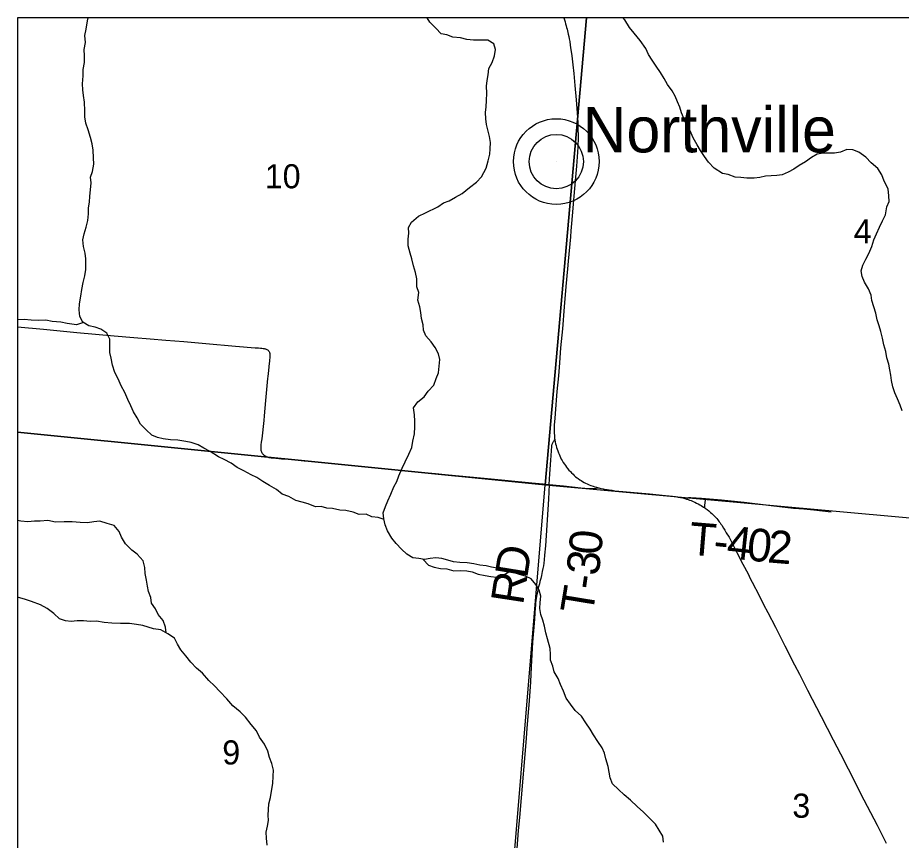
# Model space of a CAD drawing. Extents: x 0 to 1067, y 0 to 440.
# Drawn here: x 798.04 to 799.575, y 356.173 to 357.602 of the extents above; entities that cross this region are included whole.
import ezdxf

# ---------------------------------------------------------------- set-up
doc = ezdxf.new("R2010")
doc.units = 0
for name, color, linetype in [('GM_X_Minor_River', 7, 'Continuous'), ('GM_X_Section', 7, 'Continuous'), ('GM_X_Section_Text', 7, 'Continuous'), ('GM_X_State_Route', 7, 'Continuous'), ('GM_X_Township_Road', 7, 'Continuous'), ('GM_X_Township_Road_Text', 7, 'Continuous'), ('GM_X_Unincorporated', 7, 'Continuous'), ('GM_X_Unincorporated_Location', 7, 'Continuous'), ('GM_X_Unincorporated_Text', 7, 'Continuous'), ('GM_X_US_Shield', 7, 'Continuous')]:
    doc.layers.add(name, color=color, linetype=linetype)

msp = doc.modelspace()

# ---------------------------------------------------------------- linework, layer by layer
at = {"layer": 'GM_X_Minor_River'}
for points in [[(798.1593, 357.5822), (798.1612, 357.5969), (798.1625, 357.6021)], [(798.742, 357.0794), (798.7404, 357.09), (798.7388, 357.0999), (798.7354, 357.1114), (798.7373, 357.1246), (798.7338, 357.1346), (798.7334, 357.1482), (798.7311, 357.1593), (798.7281, 357.1711), (798.725, 357.1834), (798.7222, 357.1929), (798.7185, 357.2059), (798.7184, 357.2173), (798.7195, 357.2279), (798.719, 357.2374), (798.7242, 357.2471), (798.7367, 357.2573), (798.7486, 357.2634), (798.7702, 357.2733), (798.7802, 357.2802), (798.7898, 357.2841), (798.8006, 357.2902), (798.8126, 357.2967), (798.8254, 357.3069), (798.8371, 357.3161), (798.8457, 357.3257), (798.8541, 357.3409), (798.8576, 357.3537), (798.8602, 357.365), (798.8608, 357.3745), (798.8615, 357.385), (798.8599, 357.3957), (798.8569, 357.4072), (798.8549, 357.4167), (798.8533, 357.4266), (798.8528, 357.4372), (798.8539, 357.447), (798.8546, 357.458), (798.855, 357.4709), (798.8549, 357.4834), (798.8556, 357.4928), (798.8574, 357.503), (798.8589, 357.5139), (798.8645, 357.5244), (798.8683, 357.5356), (798.8705, 357.5469), (798.8674, 357.5565), (798.8569, 357.5632), (798.8467, 357.5632), (798.8319, 357.5632), (798.8205, 357.5643), (798.8092, 357.5669), (798.7964, 357.5684), (798.7859, 357.5722), (798.7761, 357.574), (798.7665, 357.5841), (798.7562, 357.5943), (798.7515, 357.6021)], [(799.2503, 357.3409), (799.2404, 357.351), (799.2334, 357.3607), (799.2262, 357.3712), (799.2208, 357.3812), (799.2139, 357.3935), (799.2086, 357.4054), (799.2021, 357.4158), (799.1982, 357.4258), (799.1936, 357.4369), (799.1904, 357.4465), (799.1862, 357.4561), (799.1827, 357.4657), (799.1773, 357.4753), (799.1692, 357.4861), (799.1635, 357.4965), (799.157, 357.507), (799.1497, 357.5178), (799.1424, 357.5282), (799.1362, 357.5379), (799.1316, 357.5486), (799.1214, 357.5622), (799.1112, 357.575), (799.1031, 357.5851), (799.0948, 357.5982), (799.0919, 357.6021)], [(798.6766, 356.7304), (798.6666, 356.7338), (798.6556, 356.7353), (798.6455, 356.7398), (798.6333, 356.7394), (798.6228, 356.7431), (798.6104, 356.7458), (798.5998, 356.7465), (798.5869, 356.7495), (798.5771, 356.7502), (798.5673, 356.7532), (798.5578, 356.7527), (798.5451, 356.7576), (798.5345, 356.7606), (798.5232, 356.7632), (798.5113, 356.7704), (798.4996, 356.7746), (798.4896, 356.7828), (798.4777, 356.7893), (798.4661, 356.7965), (798.4557, 356.8032), (798.446, 356.8081), (798.4329, 356.8149), (798.4213, 356.821), (798.4109, 356.8281), (798.3989, 356.8346), (798.3892, 356.8394), (798.3743, 356.8486), (798.3635, 356.8542), (798.3538, 356.8602), (798.3418, 356.864), (798.332, 356.8662), (798.3184, 356.8685), (798.3055, 356.8689), (798.293, 356.8708), (798.2832, 356.8726), (798.2734, 356.8767), (798.2635, 356.8861), (798.2535, 356.8963), (798.2478, 356.9071), (798.2416, 356.9175), (798.237, 356.9279), (798.2313, 356.939), (798.2263, 356.9513), (798.2198, 356.9625), (798.2145, 356.9748), (798.2091, 356.986), (798.2049, 356.9986), (798.2026, 357.0108), (798.2003, 357.0207), (798.2002, 357.0321), (798.2002, 357.0439), (798.1952, 357.0539), (798.1848, 357.061), (798.1746, 357.0644), (798.1637, 357.0666), (798.1533, 357.0733), (798.1479, 357.083), (798.1471, 357.0944), (798.1474, 357.105), (798.15, 357.1182), (798.1515, 357.1302), (798.1538, 357.1423), (798.1568, 357.1536), (798.1583, 357.1649), (798.1584, 357.1831), (798.1572, 357.1933), (798.1545, 357.2044), (798.1533, 357.2162), (798.1555, 357.2264), (798.1593, 357.238), (798.1623, 357.2496), (798.163, 357.2614), (798.1633, 357.2716), (798.1651, 357.2814), (798.1654, 357.292), (798.1665, 357.3033), (798.1677, 357.3154), (798.1668, 357.3249), (798.1701, 357.335), (798.1724, 357.3474), (798.1716, 357.3584), (798.1712, 357.3721), (798.1693, 357.3827), (798.1666, 357.3938), (798.1628, 357.4072), (798.1586, 357.419), (798.157, 357.43), (798.1569, 357.4403), (798.1563, 357.4554), (798.1547, 357.4668), (798.1531, 357.4767), (798.1527, 357.4873), (798.1538, 357.5013), (798.1541, 357.5119), (798.156, 357.5243), (798.1564, 357.5361), (798.1559, 357.5471), (798.1582, 357.5591), (798.157, 357.5709), (798.1593, 357.5822)], [(799.5771, 356.9191), (799.5736, 356.9291), (799.5689, 356.9398), (799.5639, 356.9506), (799.5605, 356.9609), (799.5585, 356.9716), (799.5569, 356.9811), (799.5556, 356.9907), (799.5537, 357.0002), (799.5502, 357.0113), (799.5486, 357.022), (799.5448, 357.0338), (799.5425, 357.0453), (799.5398, 357.0571), (799.537, 357.0671), (799.5332, 357.0774), (799.5312, 357.0888), (799.5278, 357.0996), (799.5243, 357.1107), (799.5231, 357.1202), (799.5181, 357.1309), (799.5112, 357.1429), (799.5073, 357.1525), (799.5057, 357.1624), (799.5087, 357.1725), (799.5135, 357.1826), (799.5188, 357.1927), (799.5244, 357.2047), (799.5278, 357.2163), (799.5323, 357.2264), (799.5372, 357.2384), (799.5428, 357.2492), (799.5477, 357.2597), (799.5504, 357.2733), (799.5544, 357.283), (799.5536, 357.2929), (799.5524, 357.305), (799.5456, 357.3181), (799.5414, 357.3292), (799.5345, 357.3401), (799.523, 357.3499), (799.5135, 357.3596), (799.5016, 357.3687), (799.4911, 357.3724), (799.4808, 357.3731), (799.4697, 357.3685), (799.4594, 357.3665), (799.4488, 357.3665), (799.4393, 357.3667), (799.429, 357.3648), (799.4193, 357.359), (799.4089, 357.3517), (799.3981, 357.3456), (799.3884, 357.3391), (799.3787, 357.334), (799.3684, 357.3294), (799.3588, 357.3278), (799.3394, 357.3269), (799.3295, 357.3245), (799.3196, 357.3233), (799.3067, 357.3233), (799.2965, 357.3244), (799.2866, 357.325), (799.2743, 357.3296), (799.2645, 357.3317), (799.2503, 357.3409)], [(798.1547, 357.0724), (798.1421, 357.0684), (798.1262, 357.0708), (798.1149, 357.073), (798.1002, 357.0746), (798.0892, 357.0764), (798.0763, 357.0761), (798.0638, 357.0768), (798.0517, 357.078), (798.0403, 357.0772), (798.0401, 357.0772)], [(799.1611, 356.1806), (799.1545, 356.1911), (799.148, 356.2012), (799.1384, 356.211), (799.1277, 356.2223), (799.1163, 356.2322), (799.1048, 356.2428), (799.0937, 356.2522), (799.0837, 356.2616), (799.0738, 356.2714), (799.0695, 356.2815), (799.0675, 356.2914), (799.0663, 356.3013), (799.0622, 356.3147), (799.0598, 356.3243), (799.0555, 356.3339), (799.0479, 356.3448), (799.0406, 356.3564), (799.0348, 356.3661), (799.0272, 356.377), (799.0196, 356.389), (799.0085, 356.3984), (799.0008, 356.4097), (798.9928, 356.4202), (798.9882, 356.4321), (798.9832, 356.444), (798.979, 356.4544), (798.9725, 356.466), (798.9701, 356.4759), (798.9659, 356.4863), (798.9658, 356.4958), (798.965, 356.5065), (798.9609, 356.5229), (798.9578, 356.5337), (798.9555, 356.5451), (798.9524, 356.5555), (798.9489, 356.5654), (798.9476, 356.5757), (798.9479, 356.586), (798.949, 356.5973), (798.9463, 356.6077), (798.9405, 356.6173), (798.9325, 356.6271), (798.9224, 356.6319), (798.9122, 356.6349), (798.8979, 356.6395), (798.8873, 356.6406), (798.8765, 356.6455), (798.8636, 356.6474), (798.8538, 356.6499), (798.8432, 356.651), (798.8327, 356.6532), (798.8213, 356.6551), (798.8085, 356.6559), (798.7971, 356.657), (798.7873, 356.6599), (798.7772, 356.6625), (798.7666, 356.664), (798.7567, 356.6628), (798.7471, 356.6612), (798.7373, 356.6626), (798.7267, 356.664), (798.7163, 356.6701), (798.7067, 356.6787), (798.6978, 356.6885), (798.6902, 356.6982), (798.6826, 356.7109), (798.6787, 356.7209), (798.6764, 356.7316), (798.6751, 356.7423), (798.6793, 356.7532), (798.6833, 356.7629), (798.6886, 356.7745), (798.6939, 356.7869), (798.6988, 356.7966), (798.7025, 356.8063), (798.7082, 356.8194), (798.7134, 356.8307), (798.7195, 356.8441), (798.7252, 356.8557), (798.7266, 356.8667), (798.7297, 356.8795), (798.7304, 356.8912), (798.7303, 356.9015), (798.7295, 356.9125), (798.7276, 356.9243), (798.7351, 356.9347), (798.7464, 356.9435), (798.7535, 356.9535), (798.7633, 356.9635), (798.767, 356.9751), (798.7715, 356.9852), (798.7726, 356.9965), (798.7733, 357.0083), (798.7713, 357.0182), (798.7656, 357.029), (798.7583, 357.0391), (798.7495, 357.0496), (798.7452, 357.0592), (798.7448, 357.0687), (798.742, 357.0794)], [(798.2979, 356.5337), (798.297, 356.5435), (798.2928, 356.5551), (798.2844, 356.5652), (798.2793, 356.5752), (798.2728, 356.5849), (798.2712, 356.5952), (798.2673, 356.6052), (798.2657, 356.6147), (798.2637, 356.625), (798.2618, 356.6365), (798.261, 356.6471), (798.2579, 356.6586), (798.248, 356.6703), (798.2383, 356.6774), (798.2277, 356.6884), (798.2208, 356.7), (798.2165, 356.7096), (798.2077, 356.7198), (798.1957, 356.7235), (798.1829, 356.7273), (798.1726, 356.7265), (798.1615, 356.7246), (798.1487, 356.7254), (798.135, 356.7262), (798.121, 356.7262), (798.1058, 356.7259), (798.0926, 356.7286), (798.0793, 356.7275), (798.0694, 356.7274), (798.058, 356.7266), (798.0455, 356.7278), (798.0401, 356.7288)], [(798.7441, 356.6618), (798.7445, 356.6612), (798.754, 356.6511), (798.7638, 356.6474), (798.7747, 356.6451), (798.7857, 356.6448), (798.7978, 356.6414), (798.8096, 356.6418), (798.8202, 356.6411), (798.83, 356.6397), (798.8401, 356.6356), (798.8522, 356.6329), (798.8624, 356.6315), (798.8722, 356.63), (798.8818, 356.6324), (798.8934, 356.6396), (798.8936, 356.6399)], [(798.4759, 356.2265), (798.4766, 356.2364), (798.4796, 356.2477), (798.481, 356.2587), (798.4837, 356.2719), (798.4841, 356.2848), (798.4848, 356.2951), (798.4817, 356.3066), (798.4774, 356.3173), (798.4747, 356.328), (798.469, 356.3404), (798.4603, 356.3524), (798.4553, 356.3632), (798.4457, 356.3745), (798.4362, 356.387), (798.4266, 356.3964), (798.4137, 356.407), (798.4038, 356.4191), (798.3916, 356.4316), (798.3821, 356.4414), (798.3721, 356.4508), (798.3611, 356.4633), (798.3507, 356.4724), (798.3411, 356.4829), (798.3324, 356.4938), (798.3236, 356.504), (798.3178, 356.514), (798.3124, 356.5245), (798.3008, 356.532), (798.2889, 356.5388), (798.276, 356.5404), (798.2576, 356.5463), (798.2467, 356.5481), (798.2342, 356.5496), (798.219, 356.5497), (798.2035, 356.5506), (798.1906, 356.5517), (798.177, 356.5541), (798.166, 356.5533), (798.1546, 356.5547), (798.1436, 356.5547), (798.1333, 356.5531), (798.1235, 356.5546), (798.113, 356.5579), (798.103, 356.5673), (798.0911, 356.5761), (798.0799, 356.5825), (798.0642, 356.5883), (798.054, 356.5916), (798.0401, 356.5956)], [(798.4737, 356.1647), (798.4726, 356.1769), (798.4721, 356.1875), (798.4739, 356.1977), (798.4757, 356.2076), (798.4753, 356.2171), (798.4759, 356.2265)], [(799.1623, 356.17), (799.1611, 356.1806)]]:
    msp.add_lwpolyline(points, dxfattribs=at)
at = {"layer": 'GM_X_Section'}
msp.add_lwpolyline([(798.9566, 356.7904), (799.9676, 356.6989), (799.8698, 355.7001), (798.8732, 355.7891)], close=True, dxfattribs=at)
at = {"layer": 'GM_X_State_Route'}
for points in [[(798.9887, 357.6021), (798.9889, 357.6017), (798.99, 357.5981), (798.9911, 357.5948), (798.9921, 357.5916), (798.993, 357.588), (798.9939, 357.5848), (798.9947, 357.582), (798.9954, 357.5794), (798.996, 357.5763), (798.9967, 357.5735), (798.9977, 357.5692), (798.9985, 357.5651), (798.9992, 357.5606), (799.0002, 357.5542), (799.0008, 357.5503), (799.0027, 357.5358), (799.0034, 357.5307), (799.0048, 357.52), (799.0061, 357.5052), (799.0082, 357.4842), (799.0105, 357.4594), (799.0117, 357.4441), (799.0128, 357.428), (799.0131, 357.4192), (799.0135, 357.4118), (799.0137, 357.3941), (799.0132, 357.378), (799.0129, 357.3684), (799.0123, 357.3601), (799.0111, 357.3439), (799.0089, 357.3186), (799.0065, 357.292), (799.0052, 357.2783), (799.0035, 357.258), (799.0023, 357.2445), (799.0013, 357.2318), (799.0003, 357.2215), (798.9992, 357.2091), (798.9975, 357.1915), (798.9964, 357.179), (798.9952, 357.1656), (798.9927, 357.1351), (798.9896, 357.1), (798.9865, 357.0617), (798.9835, 357.0289), (798.9812, 357.0027), (798.9795, 356.9799), (798.9771, 356.9526), (798.9738, 356.9144), (798.9731, 356.9056), (798.9723, 356.895), (798.9722, 356.8886), (798.9723, 356.8818), (798.9726, 356.8754), (798.9729, 356.8719), (798.9734, 356.8688), (798.974, 356.8653), (798.9747, 356.862), (798.9755, 356.8588), (798.9763, 356.8555), (798.9773, 356.8524), (798.9783, 356.8495), (798.9796, 356.8463), (798.9807, 356.8437), (798.9818, 356.841), (798.9831, 356.8382), (798.9846, 356.8351), (798.9859, 356.8328), (798.9878, 356.8296), (798.9899, 356.8267), (798.9917, 356.8241), (798.9935, 356.8215), (798.9955, 356.8188), (798.9978, 356.8162), (799.0003, 356.8136), (799.0024, 356.8113), (799.0051, 356.8089), (799.0071, 356.8069), (799.0095, 356.8048), (799.0121, 356.8027), (799.014, 356.8015), (799.0168, 356.7996), (799.0191, 356.798), (799.0216, 356.7965), (799.0242, 356.795), (799.0269, 356.7936), (799.0296, 356.7923), (799.0329, 356.7909), (799.0359, 356.7897), (799.0398, 356.7883), (799.0429, 356.7873), (799.0459, 356.7864), (799.0497, 356.7853), (799.0531, 356.7845), (799.0573, 356.7836), (799.0611, 356.7828), (799.0644, 356.7823), (799.0678, 356.7818), (799.0727, 356.7812), (799.0777, 356.7805), (799.0917, 356.779), (799.1379, 356.7749), (799.1655, 356.7722), (799.1721, 356.7715), (799.1778, 356.7708), (799.183, 356.7702), (799.1877, 356.7694), (799.1919, 356.7687), (799.196, 356.7678), (799.1993, 356.7669), (799.2024, 356.766), (799.2052, 356.7651), (799.2076, 356.7643), (799.2105, 356.7632), (799.2137, 356.7619), (799.2167, 356.7606), (799.2196, 356.7591), (799.2225, 356.7576), (799.2251, 356.7561), (799.2278, 356.7546), (799.2319, 356.7519), (799.2338, 356.7506), (799.2347, 356.75), (799.238, 356.7476), (799.2408, 356.7454), (799.2437, 356.7428), (799.246, 356.7407), (799.2483, 356.7386), (799.2507, 356.7363), (799.2527, 356.7343), (799.2546, 356.7322), (799.2565, 356.73), (799.2577, 356.7283), (799.2591, 356.7265), (799.2606, 356.7244), (799.262, 356.7223), (799.2633, 356.7205), (799.2664, 356.7156), (799.2687, 356.7121), (799.2713, 356.7075), (799.276, 356.6995), (799.2896, 356.6734), (799.3, 356.653), (799.309, 356.6359), (799.3129, 356.6282)], [(799.3129, 356.6282), (799.3164, 356.6214), (799.3281, 356.5982), (799.336, 356.5827), (799.3433, 356.5687), (799.3565, 356.5432), (799.3728, 356.5111), (799.3899, 356.478), (799.3982, 356.4616), (799.4123, 356.4341), (799.4361, 356.388), (799.4569, 356.3477), (799.4695, 356.3234), (799.4828, 356.2973), (799.5105, 356.2436), (799.5331, 356.1994), (799.5493, 356.1683)]]:
    msp.add_lwpolyline(points, dxfattribs=at)
at = {"layer": 'GM_X_Township_Road'}
for points in [[(799.7017, 353.7093), (799.8752, 355.6984), (799.9856, 356.8149), (800.0635, 357.6021), (798.0401, 357.6021), (798.0401, 353.8616)], [(798.0401, 357.0651), (798.0848, 357.0608), (798.1431, 357.0552), (798.2075, 357.0496), (798.2417, 357.0467), (798.2704, 357.0442), (798.2974, 357.042), (798.329, 357.0394), (798.3669, 357.0361), (798.4183, 357.0317), (798.4527, 357.0288), (798.4585, 357.0284), (798.462, 357.0281), (798.4641, 357.0279), (798.4664, 357.0277), (798.4681, 357.0274), (798.4694, 357.027), (798.4707, 357.0266), (798.4721, 357.0261), (798.4732, 357.0256), (798.4742, 357.0249), (798.4751, 357.0243), (798.476, 357.0235), (798.4765, 357.0229), (798.4771, 357.0221)], [(798.4771, 357.0221), (798.4776, 357.0211), (798.4779, 357.02), (798.4781, 357.0191), (798.4783, 357.0181), (798.4783, 357.0162), (798.4783, 357.0148), (798.4782, 357.0127), (798.4781, 357.0106), (798.4778, 357.0085), (798.4775, 357.0051), (798.4772, 357.0019), (798.4758, 356.9893), (798.4746, 356.9786), (798.4744, 356.9755), (798.4709, 356.9371), (798.4686, 356.9105), (798.4679, 356.9024), (798.4642, 356.8705), (798.4634, 356.8646), (798.4628, 356.8599), (798.4627, 356.8575), (798.4626, 356.8555), (798.4625, 356.8538), (798.4626, 356.8522), (798.4628, 356.8506), (798.4632, 356.8491), (798.4636, 356.8479), (798.4644, 356.8464), (798.4653, 356.8452), (798.4662, 356.844), (798.467, 356.8432), (798.468, 356.8423), (798.4691, 356.8416), (798.4703, 356.8409), (798.4715, 356.8402), (798.4729, 356.8395), (798.4741, 356.8391), (798.4752, 356.8387), (798.4767, 356.8384), (798.4785, 356.838), (798.4804, 356.8377), (798.4831, 356.8374), (798.4886, 356.8369), (798.4983, 356.8361), (798.511, 356.835), (798.5376, 356.8326), (798.5784, 356.8286), (798.6195, 356.8246), (798.678, 356.8188), (798.6919, 356.8174), (798.7066, 356.8159), (798.7215, 356.8145), (798.766, 356.8103), (798.7888, 356.8081), (798.8627, 356.8008), (798.9278, 356.7946), (798.9398, 356.7935), (798.9529, 356.7924), (798.9635, 356.7915)], [(798.9635, 356.7915), (798.9648, 356.8095), (798.9663, 356.8337), (798.9681, 356.8577), (798.9682, 356.8587), (798.9684, 356.8597), (798.9685, 356.8606), (798.9688, 356.8613), (798.9691, 356.8622), (798.9697, 356.8636), (798.9705, 356.8649), (798.9713, 356.866), (798.9721, 356.8671), (798.9734, 356.8688)], [(798.9635, 356.7915), (798.9621, 356.7655), (798.9569, 356.6847), (798.9555, 356.6687), (798.9548, 356.6606), (798.9541, 356.6544), (798.9535, 356.6497), (798.9527, 356.6452), (798.9515, 356.6399), (798.95, 356.6334), (798.9489, 356.6281), (798.9475, 356.6228), (798.9466, 356.6187), (798.9452, 356.6137), (798.944, 356.6088), (798.943, 356.6041), (798.9422, 356.6001), (798.9416, 356.5969), (798.941, 356.5932), (798.9405, 356.59), (798.94, 356.5859), (798.9395, 356.5809), (798.9393, 356.577), (798.9386, 356.5678), (798.9378, 356.5572), (798.9373, 356.5504), (798.9348, 356.5175), (798.9321, 356.4748), (798.9309, 356.4487), (798.9286, 356.4152), (798.9275, 356.4022), (798.9248, 356.3682), (798.9233, 356.3508), (798.9222, 356.336), (798.9146, 356.2469), (798.9118, 356.2128), (798.9098, 356.1905), (798.9071, 356.159)], [(798.9635, 356.7915), (798.9885, 356.7887), (799.0184, 356.7856), (799.0329, 356.7844), (799.0376, 356.7842), (799.0417, 356.7845), (799.0453, 356.7848), (799.0497, 356.7853)], [(799.2024, 356.766), (799.2035, 356.7671), (799.2041, 356.7675), (799.2051, 356.7681), (799.2064, 356.7684), (799.2071, 356.7685), (799.2079, 356.7686), (799.2094, 356.7686), (799.2279, 356.7673), (799.2352, 356.7667)], [(799.2338, 356.7506), (799.2342, 356.7547), (799.235, 356.7648), (799.2352, 356.7667)], [(799.2352, 356.7667), (799.2628, 356.7644), (799.2737, 356.7634), (799.3022, 356.7603), (799.3445, 356.7555), (799.3681, 356.7527), (799.3883, 356.7504), (799.4057, 356.7487), (799.4231, 356.7471), (799.4537, 356.7437)]]:
    msp.add_lwpolyline(points, dxfattribs=at)
at = {"layer": 'GM_X_Unincorporated'}
for radius in [0.0744, 0.0472]:
    msp.add_circle((798.9759, 357.3521), radius, dxfattribs=at)
at = {"layer": 'GM_X_Unincorporated_Location'}
msp.add_line((798.9759, 357.3521), (798.9759, 357.3521), dxfattribs=at)
at = {"layer": 'GM_X_US_Shield'}
for points in [[(799.0281, 357.6021), (798.0401, 357.6021), (798.0401, 356.882), (798.9566, 356.7904)], [(800.056, 357.6021), (799.0281, 357.6021), (798.9566, 356.7904), (799.9676, 356.6989)], [(798.0401, 356.882), (798.0401, 355.8691), (798.8732, 355.7891), (798.9566, 356.7904)]]:
    msp.add_lwpolyline(points, close=True, dxfattribs=at)

# ---------------------------------------------------------------- texts
at = {"layer": 'GM_X_Section_Text'}
for s, height, p in [('10', 0.04186, (798.4694, 357.3057)), ('4', 0.0419, (799.4927, 357.2102)), ('9', 0.0419, (798.3956, 356.3049)), ('3', 0.0419, (799.386, 356.2124))]:
    msp.add_text(s, height=height, rotation=0, dxfattribs=at).set_placement(p)
at = {"layer": 'GM_X_Township_Road_Text'}
for s, rotation, p in [('T', 355.2549, (799.2052, 356.6696)), ('0', 84.5531, (799.0536, 356.6676)), ('4', 353.8684, (799.2704, 356.6637)), ('0', 353.9572, (799.3053, 356.6599)), ('2', 355.2137, (799.3415, 356.6561)), ('D', 80.8581, (798.9251, 356.6269)), ('-', 353.8995, (799.2472, 356.6661)), ('3', 83.1834, (799.0493, 356.6314)), ('R', 81.3256, (798.9181, 356.5809)), ('-', 81.8311, (799.0458, 356.6068)), ('T', 80.711, (799.0387, 356.5637))]:
    msp.add_text(s, height=0.0568, rotation=rotation, dxfattribs=at).set_placement(p)
at = {"layer": 'GM_X_Unincorporated_Text'}
msp.add_text('Northville', height=0.07898, rotation=0, dxfattribs=at).set_placement((799.0215, 357.3681))

doc.saveas('drawing.dxf')
